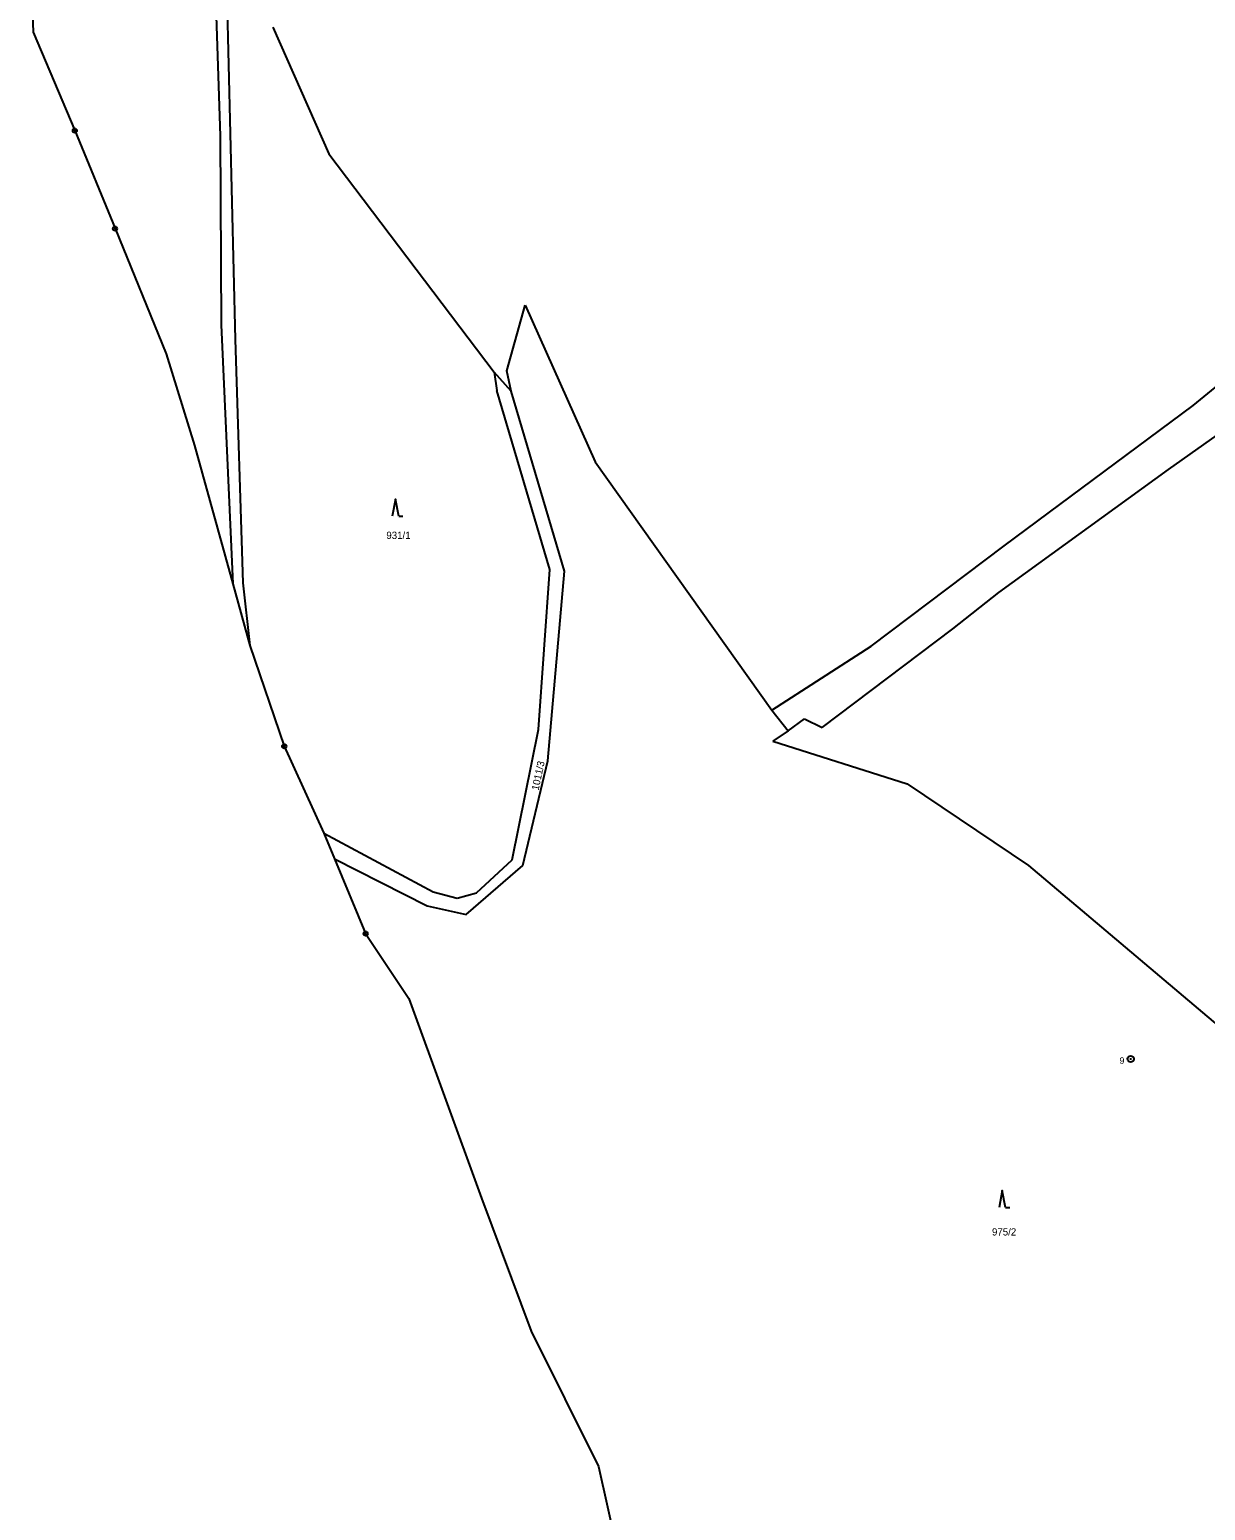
# Model space of a CAD drawing. Extents: x -744132 to -742433, y -984679 to -982287.
# Drawn here: x -743996.6 to -743720.7, y -983707.4 to -983360 of the extents above; entities that cross this region are included whole.
import ezdxf
from ezdxf.enums import TextEntityAlignment as Align

# ---------------------------------------------------------------- set-up
doc = ezdxf.new("R2010")
doc.units = 0
doc.header["$LTSCALE"] = 0.68
for name, color, linetype, lineweight in [('1', 7, 'Continuous', 25), ('3', 7, 'Continuous', 25), ('8', 7, 'Continuous', 25)]:
    doc.layers.add(name, color=color, linetype=linetype, lineweight=lineweight)
doc.layers.add('2', color=7, linetype='Continuous')

msp = doc.modelspace()

# ---------------------------------------------------------------- linework, layer by layer
at = {"layer": '1'}
for p, q in [((-743953.68, -983328.65), (-743951.88, -983384.93)), ((-743950.83, -983329.06), (-743948.3, -983432.7)), ((-743996.56, -983336.67), (-743995.72, -983360.62)), ((-743939.5, -983359.44), (-743926.31, -983389.16)), ((-743995.72, -983360.62), (-743985.95, -983383.72)), ((-743985.95, -983383.72), (-743976.52, -983406.7)), ((-743951.88, -983384.93), (-743951.61, -983429.29)), ((-743926.31, -983389.16), (-743887.56, -983440.37)), ((-743976.52, -983406.7), (-743964.49, -983436.07)), ((-743884.58, -983440.08), (-743880.3, -983424.7)), ((-743880.3, -983424.7), (-743863.84, -983461.39)), ((-743951.61, -983429.29), (-743948.87, -983490.02)), ((-743723.53, -983448.22), (-743697.32, -983426.73)), ((-743948.3, -983432.7), (-743946.53, -983489.79)), ((-743964.49, -983436.07), (-743957.84, -983457.6)), ((-743729.35, -983463.19), (-743689.92, -983435.46)), ((-743883.59, -983444.83), (-743884.58, -983440.08)), ((-743883.59, -983444.83), (-743887.56, -983440.37)), ((-743887.56, -983440.37), (-743886.95, -983444.69)), ((-743874.48, -983486.71), (-743886.95, -983444.69)), ((-743871.01, -983487.04), (-743883.59, -983444.83)), ((-743767.85, -983481.14), (-743723.53, -983448.22)), ((-743957.84, -983457.6), (-743948.87, -983490.02)), ((-743863.84, -983461.39), (-743822.36, -983519.69)), ((-743769.13, -983492.1), (-743729.35, -983463.19)), ((-743799.06, -983504.66), (-743767.85, -983481.14)), ((-743877.16, -983524.23), (-743874.48, -983486.71)), ((-743874.96, -983531.6), (-743871.01, -983487.04)), ((-743948.87, -983490.02), (-743944.87, -983504.5)), ((-743946.53, -983489.79), (-743944.87, -983504.5)), ((-743779.93, -983500.59), (-743769.13, -983492.1)), ((-743810.59, -983523.78), (-743779.93, -983500.59)), ((-743944.87, -983504.5), (-743936.8, -983528.15)), ((-743822.36, -983519.69), (-743799.06, -983504.66)), ((-743822.36, -983519.69), (-743818.54, -983524.56)), ((-743818.54, -983524.56), (-743814.72, -983521.74)), ((-743814.72, -983521.74), (-743810.59, -983523.78)), ((-743883.33, -983554.82), (-743877.16, -983524.23)), ((-743818.54, -983524.56), (-743822.16, -983526.97)), ((-743822.16, -983526.97), (-743790.65, -983537)), ((-743936.8, -983528.15), (-743927.54, -983548.54)), ((-743880.79, -983556.15), (-743874.96, -983531.6)), ((-743790.65, -983537), (-743762.21, -983556.11)), ((-743927.54, -983548.54), (-743925.03, -983554.55)), ((-743927.54, -983548.54), (-743901.85, -983562.28)), ((-743925.03, -983554.55), (-743903.29, -983565.6)), ((-743925.03, -983554.55), (-743917.71, -983572.1)), ((-743891.72, -983562.51), (-743883.33, -983554.82)), ((-743894.13, -983567.62), (-743880.79, -983556.15)), ((-743762.21, -983556.11), (-743717.8, -983593.58)), ((-743901.85, -983562.28), (-743896.26, -983563.79)), ((-743896.26, -983563.79), (-743891.72, -983562.51)), ((-743903.29, -983565.6), (-743894.13, -983567.62)), ((-743917.71, -983572.1), (-743907.56, -983587.33)), ((-743907.56, -983587.33), (-743890.56, -983634.18)), ((-743890.56, -983634.18), (-743878.84, -983665.39)), ((-743878.84, -983665.39), (-743863.09, -983697.13)), ((-743863.09, -983697.13), (-743858.44, -983717.89))]:
    msp.add_line(p, q, dxfattribs=at)
at = {"layer": '3'}
for p, q in [((-743909.95, -983474.17), (-743908.954, -983474.17)), ((-743767.58, -983636.38), (-743766.584, -983636.38))]:
    msp.add_line(p, q, dxfattribs=at)
for points in [[(-743909.95, -983474.17), (-743910.7, -983470.17), (-743911.45, -983474.17)], [(-743767.58, -983636.38), (-743768.33, -983632.38), (-743769.08, -983636.38)]]:
    msp.add_lwpolyline(points, dxfattribs=at)
at = {"layer": '8'}
for centre, radius in [((-743985.95, -983383.7199), 0.5), ((-743985.95, -983383.7199), 0.0303), ((-743976.52, -983406.6999), 0.5), ((-743976.52, -983406.6999), 0.0303), ((-743936.8, -983528.1499), 0.5), ((-743936.8, -983528.1499), 0.0303), ((-743917.71, -983572.0999), 0.5), ((-743917.71, -983572.0999), 0.0303), ((-743738.18, -983601.5198), 0.75), ((-743738.18, -983601.5198), 0.03)]:
    msp.add_circle(centre, radius, dxfattribs=at)

# ---------------------------------------------------------------- texts
at = {"layer": '2'}
for s, p in [('931/1', (-743912.85, -983479.515)), ('975/2', (-743770.74, -983642.935))]:
    msp.add_text(s, height=1.7, dxfattribs=at).set_placement(p)
msp.add_text('1011/3', height=1.7, rotation=78, dxfattribs=at).set_placement((-743877.134, -983538.618))
at = {"layer": '8'}
msp.add_text('9', height=1.5, dxfattribs=at).set_placement((-743739.68, -983602.637), align=Align.RIGHT)

doc.saveas('drawing.dxf')
